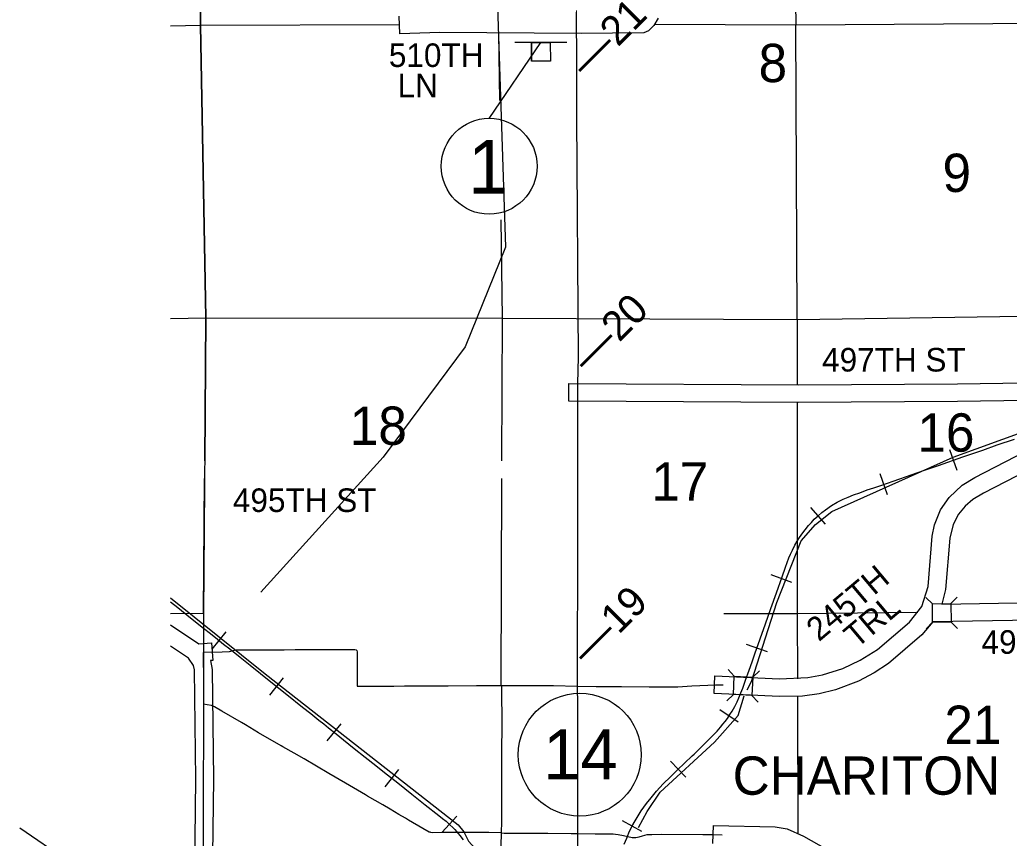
# Model space of a CAD drawing. Extents: x 10133 to 81668, y 5524 to 11018.
# Drawn here: x 18313.9 to 18733.6, y 8478.4 to 8825.6 of the extents above; entities that cross this region are included whole.
import ezdxf

# ---------------------------------------------------------------- set-up
doc = ezdxf.new("R2010")
doc.units = 0
for name, color, linetype in [('Default', 7, 'Continuous'), ('DisBoundDim', 7, 'Continuous'), ('DisCLMLOR', 7, 'Continuous'), ('DisCLMLSUR', 7, 'Continuous'), ('trf_Signal_(Temp)_Layout', 7, 'Continuous'), ('trf_SignNumber_Text', 7, 'Continuous')]:
    doc.layers.add(name, color=color, linetype=linetype)

msp = doc.modelspace()

# ---------------------------------------------------------------- linework, layer by layer
at = {"layer": 'Default'}
for p, q in [((18711.56, 8634.35), (18708.46, 8643.19)), ((18682.05, 8624.1), (18678.92, 8632.94)), ((18655.66, 8611.63), (18649.45, 8618.66)), ((18641.44, 8586.96), (18632.61, 8590.09)), ((18701.02, 8577.83), (18698.22, 8580.56)), ((18708.84, 8577.93), (18711.57, 8580.74)), ((18701.13, 8570), (18698.4, 8567.2)), ((18708.95, 8570.11), (18711.75, 8567.38)), ((18395.53, 8558.66), (18401.37, 8565.99)), ((18631.02, 8557.47), (18622.2, 8560.66)), ((18419.94, 8539.14), (18425.78, 8546.48)), ((18617.01, 8547.15), (18614.37, 8550.03)), ((18624.83, 8546.8), (18627.72, 8549.43)), ((18622.5, 8541.32), (18624.27, 8544.87)), ((18622.5, 8541.32), (18624.27, 8544.87)), ((18616.66, 8539.33), (18613.77, 8536.69)), ((18624.48, 8538.98), (18627.12, 8536.09)), ((18618.66, 8527.69), (18610.82, 8532.82)), ((18444.35, 8519.67), (18450.23, 8526.98)), ((18596.47, 8504.31), (18589.96, 8511.05)), ((18468.86, 8500.19), (18474.65, 8507.57)), ((18492.95, 8480.89), (18499.31, 8487.78)), ((18577.78, 8481.28), (18569.53, 8485.74))]:
    msp.add_line(p, q, dxfattribs=at)
for points in [[(18370.33, 9366.81), (18373.19, 9308.12), (18453.68, 9155.41), (18468.39, 9105.99), (18491.56, 8961.46), (18495.63, 8898.1), (18516.15, 8844.22), (18519.96, 8729.18), (18502.89, 8686.84), (18468.04, 8640.08), (18416.2, 8582.84)], [(18392.35, 8638.48), (18392.84, 8699.1), (18390.6, 8823.25), (18391.43, 8957.98)], [(18391.43, 8957.98), (18390.6, 8823.25)], [(18391.43, 8957.53), (18390.6, 8823.25), (18392.84, 8699.1), (18391.82, 8573.86), (18391.69, 8449.16), (18391.99, 8322.54), (18393.47, 8203.88)], [(18642.53, 8860.27), (18643.17, 8823.5)], [(18549.96, 8829.52), (18550.05, 8805.91), (18550.08, 8784.02), (18550.7, 8682.54), (18550.52, 8671.29), (18550.52, 8648.11), (18550.42, 8612.38), (18550.55, 8600.55), (18550.42, 8588.37), (18550.39, 8561.4), (18550.49, 8516.33), (18550.49, 8477.93), (18550.25, 8446.49), (18550.39, 8418.13), (18529.16, 8418.16), (18527.4, 8417.73), (18522.35, 8412.45), (18521.12, 8410.42), (18519.69, 8406.72), (18519.42, 8404.63), (18519.45, 8396.89), (18519.92, 8368.99)], [(18377.81, 8823.04), (18390.6, 8823.25)], [(18390.6, 8823.25), (18474.92, 8823.64)], [(18390.6, 8823.25), (18392.84, 8699.1)], [(18584.66, 8826.27), (18582.86, 8823.22), (18580.54, 8820.86), (18578.62, 8820.01), (18552.09, 8819.71), (18492.08, 8820.14), (18475.05, 8819.61), (18474.79, 8827.1)], [(18583.13, 8823.66), (18643.17, 8823.5)], [(18643.17, 8823.5), (18768.33, 8824.32)], [(18643.7, 8698.51), (18643.17, 8823.5)], [(18517.47, 8791.4), (18517.1, 8820.09)], [(18518.65, 8699.07), (18518.11, 8740.72)], [(18377.81, 8698.93), (18392.84, 8699.1)], [(18392.84, 8699.1), (18392.35, 8638.48)], [(18392.84, 8699.1), (18518.65, 8699.07)], [(18518.45, 8638.5), (18518.65, 8699.07)], [(18518.65, 8699.07), (18643.7, 8698.51)], [(18643.7, 8698.51), (18767.78, 8700.3)], [(18643.7, 8698.51), (18643.7, 8670.8)], [(18741.14, 8664.1), (18711.72, 8663.6), (18644.16, 8663.29), (18546.83, 8663.84), (18546.77, 8671.34), (18644.18, 8670.79), (18711.63, 8671.1), (18740.6, 8671.58)], [(18624.27, 8544.87), (18635.01, 8578.45), (18645.39, 8604.53), (18651.48, 8611.45), (18658.37, 8617), (18709.8, 8639.99), (18792.63, 8670.07)], [(18624.27, 8544.87), (18635.01, 8578.45), (18645.39, 8604.53), (18651.48, 8611.45), (18658.37, 8617), (18709.8, 8639.99), (18792.63, 8670.07)], [(18643.71, 8663.3), (18643.73, 8573.71)], [(18777.1, 8571.47), (18701.19, 8570.18), (18696.54, 8564.63), (18682.44, 8552.58), (18676.28, 8548.58), (18669.65, 8545.07), (18659.95, 8541.41), (18652.95, 8539.71), (18645.9, 8538.68), (18636.17, 8538.49), (18608.47, 8539.83), (18608.72, 8547.33), (18636.24, 8545.99), (18648.24, 8546.53), (18654.39, 8547.67), (18663.1, 8550.41), (18670.44, 8553.91), (18677.77, 8558.46), (18691.34, 8570.04), (18696.53, 8576.74), (18699.21, 8585.15), (18701, 8606.51), (18701.98, 8611.39), (18704.54, 8617.75), (18708.1, 8622.92), (18713.73, 8628.17), (18719.1, 8631.37), (18771.11, 8658.24)], [(18788.62, 8658.74), (18722.71, 8624.8), (18718.19, 8622.14), (18714.88, 8619.25), (18712.14, 8615.94), (18709.85, 8611.53), (18708.46, 8605.75), (18706.62, 8583.93), (18704.99, 8577.72), (18776.99, 8578.97)], [(18570.3, 8475.89), (18571.35, 8478.51), (18572.33, 8480.74), (18573.57, 8483.36), (18574.88, 8485.79), (18576.19, 8487.92), (18577.47, 8489.98), (18578.62, 8491.65), (18579.77, 8493.19), (18581.67, 8495.52), (18584.06, 8498.4), (18586.84, 8501.45), (18589.99, 8504.53), (18592.91, 8507.38), (18595.89, 8510.26), (18599.2, 8513.35), (18599.99, 8514.13), (18604.08, 8518.16), (18607.16, 8521.31), (18609.72, 8523.9), (18611.16, 8525.53), (18612.2, 8526.78), (18613.12, 8528), (18614.1, 8529.27), (18615.15, 8530.88), (18616.1, 8532.32), (18617.21, 8534.35), (18618.2, 8536.25), (18618.98, 8538.02), (18619.8, 8540.09), (18620.59, 8542.12), (18621.77, 8545.4), (18623.28, 8549.69), (18624.55, 8553.26), (18625.73, 8556.64), (18628.03, 8562.99), (18630.29, 8569.41), (18632.48, 8575.8), (18634.91, 8582.55), (18637.3, 8589.3), (18638.74, 8593.34), (18640.15, 8597.3), (18640.84, 8598.94), (18641.66, 8600.64), (18642.67, 8602.77), (18643.66, 8604.38), (18644.71, 8606.05), (18646.05, 8607.92), (18647.1, 8609.29), (18648.47, 8611.06), (18649.69, 8612.37), (18650.93, 8613.72), (18652.6, 8615.19), (18654.14, 8616.6), (18655.68, 8617.78), (18658.24, 8619.55), (18660.6, 8620.93), (18663.12, 8622.27), (18665.25, 8623.15), (18667.51, 8624.01), (18670.3, 8624.99), (18673.44, 8626.14), (18676.26, 8627.09), (18677.93, 8627.64), (18679.21, 8628.07), (18687.17, 8630.89), (18692.02, 8632.59), (18697.72, 8634.56), (18703.69, 8636.56), (18713.98, 8640.16), (18722.43, 8643.04), (18728.59, 8645.24), (18735.86, 8647.7)], [(18570.3, 8475.89), (18571.35, 8478.51), (18572.33, 8480.74), (18573.57, 8483.36), (18574.88, 8485.79), (18576.19, 8487.92), (18577.47, 8489.98), (18578.62, 8491.65), (18579.77, 8493.19), (18581.67, 8495.52), (18584.06, 8498.4), (18586.84, 8501.45), (18589.99, 8504.53), (18592.91, 8507.38), (18595.89, 8510.26), (18599.2, 8513.35), (18599.99, 8514.13), (18604.08, 8518.16), (18607.16, 8521.31), (18609.72, 8523.9), (18611.16, 8525.53), (18612.2, 8526.78), (18613.12, 8528), (18614.1, 8529.27), (18615.15, 8530.88), (18616.1, 8532.32), (18617.21, 8534.35), (18618.2, 8536.25), (18618.98, 8538.02), (18619.8, 8540.09), (18620.59, 8542.12), (18621.77, 8545.4), (18623.28, 8549.69), (18624.55, 8553.26), (18625.73, 8556.64), (18628.03, 8562.99), (18630.29, 8569.41), (18632.48, 8575.8), (18634.91, 8582.55), (18637.3, 8589.3), (18638.74, 8593.34), (18640.15, 8597.3), (18640.84, 8598.94), (18641.66, 8600.64), (18642.67, 8602.77), (18643.66, 8604.38), (18644.71, 8606.05), (18646.05, 8607.92), (18647.1, 8609.29), (18648.47, 8611.06), (18649.69, 8612.37), (18650.93, 8613.72), (18652.6, 8615.19), (18654.14, 8616.6), (18655.68, 8617.78), (18658.24, 8619.55), (18660.6, 8620.93), (18663.12, 8622.27), (18665.25, 8623.15), (18667.51, 8624.01), (18670.3, 8624.99), (18673.44, 8626.14), (18676.26, 8627.09), (18677.93, 8627.64), (18679.21, 8628.07), (18687.17, 8630.89), (18692.02, 8632.59), (18697.72, 8634.56), (18703.69, 8636.56), (18713.98, 8640.16), (18722.43, 8643.04), (18728.59, 8645.24), (18735.86, 8647.7)], [(18570.3, 8475.89), (18571.35, 8478.51), (18572.33, 8480.74), (18573.57, 8483.36), (18574.88, 8485.79), (18576.19, 8487.92), (18577.47, 8489.98), (18578.62, 8491.65), (18579.77, 8493.19), (18581.67, 8495.52), (18584.06, 8498.4), (18586.84, 8501.45), (18589.99, 8504.53), (18592.91, 8507.38), (18595.89, 8510.26), (18599.2, 8513.35), (18599.99, 8514.13), (18604.08, 8518.16), (18607.16, 8521.31), (18609.72, 8523.9), (18611.16, 8525.53), (18612.2, 8526.78), (18613.12, 8528), (18614.1, 8529.27), (18615.15, 8530.88), (18616.1, 8532.32), (18617.21, 8534.35), (18618.2, 8536.25), (18618.98, 8538.02), (18619.8, 8540.09), (18620.59, 8542.12), (18621.77, 8545.4), (18623.28, 8549.69), (18624.55, 8553.26), (18625.73, 8556.64), (18628.03, 8562.99), (18630.29, 8569.41), (18632.48, 8575.8), (18634.91, 8582.55), (18637.3, 8589.3), (18638.74, 8593.34), (18640.15, 8597.3), (18640.84, 8598.94), (18641.66, 8600.64), (18642.67, 8602.77), (18643.66, 8604.38), (18644.71, 8606.05), (18646.05, 8607.92), (18647.1, 8609.29), (18648.47, 8611.06), (18649.69, 8612.37), (18650.93, 8613.72), (18652.6, 8615.19), (18654.14, 8616.6), (18655.68, 8617.78), (18658.24, 8619.55), (18660.6, 8620.93), (18663.12, 8622.27), (18665.25, 8623.15), (18667.51, 8624.01), (18670.3, 8624.99), (18673.44, 8626.14), (18676.26, 8627.09), (18677.93, 8627.64), (18679.21, 8628.07), (18687.17, 8630.89), (18692.02, 8632.59), (18697.72, 8634.56), (18703.69, 8636.56), (18713.98, 8640.16), (18722.43, 8643.04), (18728.59, 8645.24), (18735.86, 8647.7)], [(18391.79, 8573.86), (18392.29, 8630.98)], [(18392.29, 8630.99), (18391.83, 8574.14)], [(18518.14, 8543.16), (18518.42, 8631)], [(18377.81, 8580.32), (18418.01, 8548.19), (18499.93, 8484.11), (18502.3, 8481.16), (18504.29, 8477.22), (18507.26, 8473.87), (18508.86, 8469.93), (18510.53, 8441.72), (18512.12, 8436.99), (18514.11, 8431.67), (18523.83, 8417.09), (18563.25, 8372.62), (18565.44, 8369.27), (18569.4, 8363.96), (18575.14, 8358.84), (18603.64, 8324.17)], [(18377.81, 8580.32), (18418.01, 8548.19), (18499.93, 8484.11), (18502.3, 8481.16), (18504.29, 8477.22), (18507.26, 8473.87), (18508.86, 8469.93), (18510.53, 8441.72), (18512.12, 8436.99), (18514.11, 8431.67), (18523.83, 8417.09), (18563.25, 8372.62), (18565.44, 8369.27), (18569.4, 8363.96), (18575.14, 8358.84), (18603.64, 8324.17)], [(18377.81, 8578.72), (18380.9, 8576.26), (18386.34, 8571.89), (18391.79, 8567.53), (18394.75, 8565.22), (18397.72, 8562.91), (18400.37, 8560.8), (18403.02, 8558.69), (18407.31, 8555.26), (18411.61, 8551.84), (18416.01, 8548.3), (18420.42, 8544.76), (18427.15, 8539.4), (18433.87, 8534.04), (18437.34, 8531.29), (18440.8, 8528.54), (18442.85, 8526.89), (18444.91, 8525.24), (18448.04, 8522.72), (18451.17, 8520.2), (18455.8, 8516.54), (18460.43, 8512.87), (18464.89, 8509.32), (18469.35, 8505.77), (18471.79, 8503.85), (18474.24, 8501.93), (18477.19, 8499.55), (18480.14, 8497.18), (18485.93, 8492.6), (18491.72, 8488.02), (18493.22, 8486.83), (18494.73, 8485.63), (18496.21, 8484.27), (18497.69, 8482.9), (18498.46, 8482.11), (18499.22, 8481.32), (18500.59, 8479.53), (18501.96, 8477.75)], [(18377.81, 8578.72), (18380.9, 8576.26), (18386.34, 8571.89), (18391.79, 8567.53), (18394.75, 8565.22), (18397.72, 8562.91), (18400.37, 8560.8), (18403.02, 8558.69), (18407.31, 8555.26), (18411.61, 8551.84), (18416.01, 8548.3), (18420.42, 8544.76), (18427.15, 8539.4), (18433.87, 8534.04), (18437.34, 8531.29), (18440.8, 8528.54), (18442.85, 8526.89), (18444.91, 8525.24), (18448.04, 8522.72), (18451.17, 8520.2), (18455.8, 8516.54), (18460.43, 8512.87), (18464.89, 8509.32), (18469.35, 8505.77), (18471.79, 8503.85), (18474.24, 8501.93), (18477.19, 8499.55), (18480.14, 8497.18), (18485.93, 8492.6), (18491.72, 8488.02), (18493.22, 8486.83), (18494.73, 8485.63), (18496.21, 8484.27), (18497.69, 8482.9), (18498.46, 8482.11), (18499.22, 8481.32), (18500.59, 8479.53), (18501.96, 8477.75)], [(18377.81, 8578.72), (18380.9, 8576.26), (18386.34, 8571.89), (18391.79, 8567.53), (18394.75, 8565.22), (18397.72, 8562.91), (18400.37, 8560.8), (18403.02, 8558.69), (18407.31, 8555.26), (18411.61, 8551.84), (18416.01, 8548.3), (18420.42, 8544.76), (18427.15, 8539.4), (18433.87, 8534.04), (18437.34, 8531.29), (18440.8, 8528.54), (18442.85, 8526.89), (18444.91, 8525.24), (18448.04, 8522.72), (18451.17, 8520.2), (18455.8, 8516.54), (18460.43, 8512.87), (18464.89, 8509.32), (18469.35, 8505.77), (18471.79, 8503.85), (18474.24, 8501.93), (18477.19, 8499.55), (18480.14, 8497.18), (18485.93, 8492.6), (18491.72, 8488.02), (18493.22, 8486.83), (18494.73, 8485.63), (18496.21, 8484.27), (18497.69, 8482.9), (18498.46, 8482.11), (18499.22, 8481.32), (18500.59, 8479.53), (18501.96, 8477.75)], [(18377.81, 8573.76), (18391.79, 8573.86)], [(18612.61, 8573.72), (18643.73, 8573.71)], [(18643.73, 8573.71), (18694.88, 8574.26)], [(18643.73, 8573.71), (18643.79, 8546.08)], [(18377.81, 8568.91), (18389.81, 8560.82), (18395.27, 8561.34), (18395.8, 8553.86), (18394.76, 8553.79), (18395.55, 8550.06), (18396.11, 8503.43), (18395.22, 8439.18), (18387.73, 8439.34), (18387.86, 8445.39), (18377.81, 8445.18)], [(18377.81, 8452.68), (18388, 8452.89), (18388.61, 8503.45), (18388.05, 8549.8), (18387.52, 8551.75), (18385.41, 8554.74), (18377.81, 8559.82)], [(18391.8, 8557.33), (18399.71, 8557.53), (18402.8, 8557.68), (18404.42, 8558.02), (18405.69, 8558.3), (18407.05, 8558.39), (18410.93, 8558.36), (18425.64, 8558.39), (18426.03, 8558.39), (18430.74, 8558.47), (18433.5, 8558.51), (18439.32, 8558.53), (18442.75, 8558.54), (18448.02, 8558.54), (18453.13, 8558.54), (18456.09, 8558.51), (18456.53, 8558.39), (18456.76, 8558.13), (18456.83, 8558.05), (18457.02, 8557.53), (18456.99, 8554.84), (18457, 8551.28), (18457.02, 8548.19), (18456.98, 8542.9), (18459.48, 8542.91), (18464.56, 8542.94), (18472.51, 8542.98), (18477.15, 8543.01), (18481.22, 8543.03), (18485.52, 8543.05), (18487.45, 8543.06), (18494.02, 8543.09), (18495.5, 8543.1), (18495.58, 8543.1), (18507.63, 8543.16), (18509.06, 8543.16), (18518.38, 8543.18)], [(18391.79, 8550.86), (18391.79, 8557.14)], [(18518.21, 8480.66), (18518.36, 8485.52), (18518.45, 8488.54), (18518.44, 8490.71), (18518.42, 8496.43), (18518.39, 8501.33), (18518.39, 8502.47), (18518.45, 8511.07), (18518.45, 8511.98), (18518.42, 8519.18), (18518.46, 8522.44), (18518.51, 8527.44), (18518.47, 8533), (18518.45, 8535.39), (18518.38, 8543.18)], [(18518.38, 8543.18), (18522.62, 8543.19), (18528.3, 8543.19), (18538.06, 8543.19), (18540.25, 8543.19), (18550.38, 8542.95), (18558.44, 8542.76), (18559.73, 8542.76), (18568.85, 8542.73), (18569.2, 8542.73), (18580.88, 8542.67), (18589.57, 8542.57), (18593.05, 8542.7), (18598.94, 8543.04), (18605.75, 8543.41), (18608.96, 8543.53), (18611.95, 8543.47), (18612.34, 8543.46)], [(18576.31, 8482.96), (18580.04, 8489.69), (18585.54, 8497.99), (18608.56, 8519.17), (18618.59, 8530.45), (18621.13, 8538.75)], [(18576.31, 8482.96), (18580.04, 8489.69), (18585.54, 8497.99), (18608.56, 8519.17), (18618.59, 8530.45), (18621.13, 8538.75)], [(18643.8, 8538.57), (18643.92, 8480.59)], [(18518.21, 8480.66), (18518.21, 8480.66), (18512.84, 8480.86), (18508.68, 8480.85), (18507.79, 8480.85), (18497.37, 8480.83), (18496.9, 8480.83), (18493.24, 8480.79), (18489.04, 8480.74), (18488.21, 8480.86), (18487.96, 8480.94), (18487.59, 8481.05), (18480.55, 8485.14), (18478.85, 8486.13), (18477.51, 8486.9), (18474.72, 8488.53), (18471.01, 8490.7), (18467.86, 8492.54), (18461.37, 8496.32), (18460.56, 8496.8), (18457.21, 8498.76), (18452.02, 8501.82), (18444.96, 8505.86), (18434.54, 8512.03), (18430.27, 8514.45), (18425.48, 8517.17), (18424.71, 8517.62), (18415.21, 8523.15), (18409.69, 8526.45), (18407.93, 8527.48), (18399.55, 8532.37), (18396.44, 8534.13), (18395.17, 8534.71), (18393.42, 8535.05), (18391.77, 8535.26)], [(18607.96, 8476.25), (18608.14, 8483.75), (18634.39, 8483.19), (18639.44, 8482.4), (18646.39, 8479.35), (18687.6, 8455.98)], [(18518.23, 8448.58), (18518.2, 8456.57), (18518.2, 8458.37), (18518.2, 8460.95), (18518.11, 8467.64), (18518.11, 8468.24), (18518.05, 8475.25), (18518.21, 8480.66)], [(18518.21, 8480.66), (18519.43, 8480.61), (18528.12, 8480.58), (18528.12, 8480.58), (18537.88, 8480.53), (18547.82, 8480.49), (18550.48, 8480.45), (18557.93, 8480.31), (18559.89, 8480.29), (18565.68, 8480.24), (18566.65, 8480.2), (18567.67, 8480.06), (18570, 8479.6), (18573.72, 8478.8), (18574.51, 8478.73), (18575.26, 8478.71), (18576, 8478.82), (18576.68, 8478.97), (18578.01, 8479.43), (18579.11, 8479.74), (18580.11, 8479.95), (18582, 8480.02), (18586.27, 8480.09), (18603.72, 8480.02), (18608.15, 8480), (18611.8, 8479.91)]]:
    msp.add_lwpolyline(points, dxfattribs=at)
for points in [[(18701.02, 8577.83), (18708.84, 8577.93), (18708.95, 8570.11), (18701.13, 8570)], [(18617.01, 8547.15), (18624.83, 8546.8), (18624.48, 8538.98), (18616.66, 8539.33)]]:
    msp.add_lwpolyline(points, close=True, dxfattribs=at)
msp.add_circle((18551.44, 8513.86), 26.06, dxfattribs=at)
at = {"layer": 'DisBoundDim'}
for p, q in [((18546.03, 8816), (18523.89, 8815.96)), ((18530.96, 8815.97), (18530.97, 8807.97)), ((18538.96, 8815.99), (18538.97, 8807.99)), ((18538.97, 8807.99), (18530.97, 8807.97))]:
    msp.add_line(p, q, dxfattribs=at)
at = {"layer": 'DisCLMLOR'}
for p, q in [((18530.96, 8815.97), (18538.96, 8815.99)), ((18530.96, 8815.97), (18538.96, 8815.99)), ((18530.96, 8815.97), (18538.96, 8815.99)), ((18530.96, 8815.97), (18538.96, 8815.99)), ((18530.97, 8807.97), (18530.96, 8815.97)), ((18530.97, 8807.97), (18530.96, 8815.97)), ((18530.97, 8807.97), (18530.96, 8815.97)), ((18530.97, 8807.97), (18530.96, 8815.97)), ((18538.96, 8815.99), (18538.97, 8807.99)), ((18538.96, 8815.99), (18538.97, 8807.99)), ((18538.96, 8815.99), (18538.97, 8807.99)), ((18538.96, 8815.99), (18538.97, 8807.99)), ((18538.97, 8807.99), (18530.97, 8807.97)), ((18538.97, 8807.99), (18530.97, 8807.97)), ((18538.97, 8807.99), (18530.97, 8807.97)), ((18538.97, 8807.99), (18530.97, 8807.97))]:
    msp.add_line(p, q, dxfattribs=at)
at = {"layer": 'DisCLMLSUR'}
msp.add_line((18513.02, 8783.78), (18534.96, 8815.98), dxfattribs=at)
at = {"layer": 'trf_Signal_(Temp)_Layout'}
msp.add_line((18378.06, 8439.12), (18313.89, 8482.66), dxfattribs=at)
at = {"layer": 'trf_SignNumber_Text'}
msp.add_circle((18513.02, 8763.46), 20.33, dxfattribs=at)

# ---------------------------------------------------------------- texts
at = {"layer": 'Default'}
for s, height, rotation, p in [('‒‒21', 12.5, 45, (18554.47, 8800.62)), ('8', 16.25, 0.0079, (18627.32, 8799.14)), ('9', 16.25, 0.0086, (18705.34, 8752.54)), ('‒‒20', 12.5, 45, (18555.07, 8675.4)), ('18', 16.25, 0.0072, (18453.93, 8645.27)), ('16', 16.25, 0.0086, (18694.72, 8642.39)), ('17', 16.25, 0.0079, (18581.83, 8621.61)), ('245TH', 10, 40.0406, (18652.89, 8561.54)), ('‒‒19', 12.5, 45, (18554.79, 8551.39)), (' TRL', 10, 40.0406, (18666.05, 8556.27)), ('490TH ST', 10, 0.2303, (18721.9, 8556.61)), ('21', 16.25, 0.0086, (18706.15, 8518.42)), ('CHARITON', 16.25, 0.0084, (18616.31, 8496.86))]:
    msp.add_text(s, height=height, rotation=rotation, dxfattribs=at).set_placement(p)
for s, height, p in [('510TH', 10, (18470.46, 8805.56)), (' LN', 10, (18470.46, 8792.66)), ('497TH ST', 10, (18654.25, 8676.38)), ('495TH ST', 10, (18404.29, 8616.8)), ('14', 21.25, (18535.96, 8503.37))]:
    msp.add_text(s, height=height, dxfattribs=at).set_placement(p)
at = {"layer": 'trf_SignNumber_Text'}
msp.add_text('1', height=22.82, dxfattribs=at).set_placement((18504.12, 8751.84))

doc.saveas('drawing.dxf')
